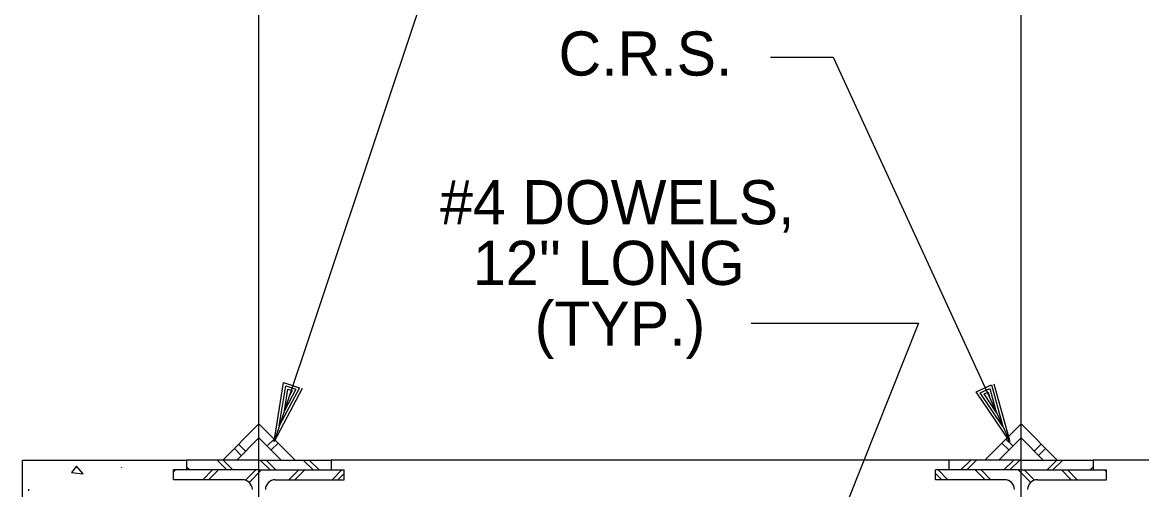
# Model space of a CAD drawing. Extents: x 0 to 320, y -4 to 473.
# Drawn here: x 9.886 to 13.435, y 16.424 to 17.904 of the extents above; entities that cross this region are included whole.
import ezdxf

# ---------------------------------------------------------------- set-up
doc = ezdxf.new("R2010")
doc.units = 0
for name, color, linetype in [('Level 10', 7, 'Continuous'), ('Level 2', 7, 'Continuous'), ('Level 3', 7, 'Continuous')]:
    doc.layers.add(name, color=color, linetype=linetype)

msp = doc.modelspace()

# ---------------------------------------------------------------- linework, layer by layer
at = {"layer": 'Level 10'}
for p, q in [((10.2013, 16.4925), (10.2001, 16.4948)), ((9.9062, 16.4199), (9.9058, 16.425))]:
    msp.add_line(p, q, dxfattribs=at)
msp.add_lwpolyline([(10.0785, 16.4738), (10.0579, 16.4975), (10.0413, 16.4778)], close=True, dxfattribs=at)
at = {"layer": 'Level 2'}
for p, q in [((10.6358, 16.6319), (10.5212, 16.5173)), ((10.6358, 16.6319), (10.7504, 16.5173)), ((13.0525, 16.6319), (12.9379, 16.5173)), ((13.0525, 16.6319), (13.1671, 16.5173)), ((10.6358, 16.5877), (10.5654, 16.5173)), ((10.6358, 16.5877), (10.7062, 16.5173)), ((10.6618, 16.5618), (10.6839, 16.5839)), ((13.0525, 16.5877), (12.9821, 16.5173)), ((13.0266, 16.5618), (13.0045, 16.5839)), ((13.0525, 16.5877), (13.1229, 16.5173)), ((10.5801, 16.532), (10.558, 16.5541)), ((10.5936, 16.5455), (10.5715, 16.5676)), ((10.6744, 16.5491), (10.6965, 16.5712)), ((13.0139, 16.5491), (12.9918, 16.5712)), ((13.0947, 16.5455), (13.1168, 16.5676)), ((13.1082, 16.532), (13.1303, 16.5541)), ((9.8858, 16.5173), (10.4067, 16.5173)), ((9.8858, 14.1673), (9.8858, 16.5173)), ((10.6358, 16.5173), (10.4067, 16.5173)), ((10.4067, 16.5173), (10.4067, 16.4861)), ((10.5344, 16.4861), (10.5031, 16.5173)), ((10.5532, 16.4861), (10.522, 16.5173)), ((10.6358, 16.5173), (10.865, 16.5173)), ((10.6711, 16.4861), (10.6398, 16.5173)), ((10.6899, 16.4861), (10.6587, 16.5173)), ((10.8078, 16.4861), (10.7765, 16.5173)), ((10.8266, 16.4861), (10.7954, 16.5173)), ((10.865, 16.5173), (10.865, 16.4861)), ((12.8233, 16.5173), (10.865, 16.5173)), ((13.0525, 16.5173), (12.8233, 16.5173)), ((12.8233, 16.5173), (12.8233, 16.4861)), ((12.8617, 16.4861), (12.8929, 16.5173)), ((12.8805, 16.4861), (12.9118, 16.5173)), ((12.9984, 16.4861), (13.0296, 16.5173)), ((13.0172, 16.4861), (13.0485, 16.5173)), ((13.0525, 16.5173), (13.2817, 16.5173)), ((13.1351, 16.4861), (13.1663, 16.5173)), ((13.1539, 16.4861), (13.1852, 16.5173)), ((13.2817, 16.5173), (13.2817, 16.4861)), ((15.7608, 16.5173), (13.2817, 16.5173)), ((10.6358, 16.4861), (10.365, 16.4861)), ((10.365, 16.4548), (10.365, 16.4861)), ((10.365, 16.48), (10.371, 16.4861)), ((10.4165, 16.4861), (10.4067, 16.4959)), ((10.4576, 16.4548), (10.4889, 16.4861)), ((10.4765, 16.4548), (10.5078, 16.4861)), ((10.593, 16.4534), (10.6256, 16.4861)), ((10.6049, 16.4466), (10.6445, 16.4861)), ((10.6358, 16.4861), (10.9067, 16.4861)), ((10.7311, 16.4548), (10.7623, 16.4861)), ((10.7499, 16.4548), (10.7812, 16.4861)), ((10.8678, 16.4548), (10.899, 16.4861)), ((10.8866, 16.4548), (10.9067, 16.4749)), ((10.9067, 16.4548), (10.9067, 16.4861)), ((13.0525, 16.4861), (12.7817, 16.4861)), ((12.7817, 16.4548), (12.7817, 16.4861)), ((12.8017, 16.4548), (12.7817, 16.4749)), ((12.8205, 16.4548), (12.7893, 16.4861)), ((12.9384, 16.4548), (12.9071, 16.4861)), ((12.9573, 16.4548), (12.926, 16.4861)), ((13.0834, 16.4466), (13.0439, 16.4861)), ((13.0525, 16.4861), (13.3233, 16.4861)), ((13.0954, 16.4534), (13.0627, 16.4861)), ((13.2118, 16.4548), (13.1806, 16.4861)), ((13.2307, 16.4548), (13.1994, 16.4861)), ((13.2718, 16.4861), (13.2817, 16.4959)), ((13.3233, 16.48), (13.3173, 16.4861)), ((13.3233, 16.4548), (13.3233, 16.4861)), ((10.5837, 16.4548), (10.365, 16.4548)), ((10.6879, 16.4548), (10.9067, 16.4548)), ((13.0004, 16.4548), (12.7817, 16.4548)), ((13.1046, 16.4548), (13.3233, 16.4548))]:
    msp.add_line(p, q, dxfattribs=at)
for centre, start, end in [((10.5837, 16.4236), 0, 90), ((10.6879, 16.4236), 90, 180), ((13.0004, 16.4236), 0, 90), ((13.1046, 16.4236), 90, 180)]:
    msp.add_arc(centre, 0.0313, start, end, dxfattribs=at)
at = {"layer": 'Level 3'}
for p, q in [((10.6358, 16.3189), (10.6358, 19.1678)), ((13.0525, 16.3341), (13.0525, 19.177)), ((10.7006, 16.6255), (10.7006, 16.6255)), ((12.995, 16.6235), (12.995, 16.6235)), ((10.6842, 16.5762), (10.6842, 16.5762)), ((13.0167, 16.5762), (13.0167, 16.5762))]:
    msp.add_line(p, q, dxfattribs=at)
for points in [[(11.3953, 17.9965), (11.1583, 17.9965), (10.6842, 16.5762)], [(12.2581, 17.7936), (12.4573, 17.7936), (13.0167, 16.5762)], [(12.1967, 16.9511), (12.7269, 16.9511), (12.281, 15.831)], [(10.7728, 16.7438), (10.6842, 16.5762), (10.714, 16.7634), (10.7642, 16.7466), (10.7006, 16.6255), (10.7209, 16.7527), (10.7532, 16.7419), (10.7165, 16.673), (10.7279, 16.7419), (10.7412, 16.7375), (10.7329, 16.7223)], [(12.9668, 16.7591), (13.0167, 16.5762), (12.9104, 16.7332), (12.9586, 16.7553), (12.995, 16.6235), (12.9229, 16.7301), (12.9538, 16.7443), (12.9741, 16.6689), (12.9353, 16.727), (12.948, 16.7329), (12.9524, 16.7162)]]:
    msp.add_lwpolyline(points, dxfattribs=at)

# ---------------------------------------------------------------- texts
for s, p in [('C.R.S.', (11.586, 17.7357)), ('#4 DOWELS,', (11.2104, 17.2644)), ("12'' LONG", (11.3146, 17.0721)), ('(TYP.)', (11.5103, 16.8797))]:
    msp.add_text(s, height=0.14, dxfattribs=at).set_placement(p)

doc.saveas('drawing.dxf')
